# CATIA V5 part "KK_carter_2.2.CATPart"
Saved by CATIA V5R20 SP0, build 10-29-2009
Part number: carter_2.2
Bounding box of the stored display mesh (mm): x -14.5 to 19.5, y 75 to 250, z -25 to 50
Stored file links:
  G:\Khaled_CFAO_2011\ST2M\ST2M_GR2\aandujar\Khaled\CAD_thinkMOTION\KK_carter_2.2.CATPart
  G:\Khaled_CFAO_2011\ST2M\ST2M_GR2\aandujar\Khaled\CAD_thinkMOTION\KK_Aandujar.CATProduct
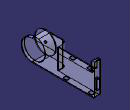
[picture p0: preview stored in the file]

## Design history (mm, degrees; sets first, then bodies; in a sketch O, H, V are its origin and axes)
WSupportSet1: ActiveGrid {3dwsupport RefPoint {point stored without definition}, 3DWOS ({wsupport Support xy-plane, RefPoint {3dwsupport}, GridIn {cartgrid Value 100, Stepbid1 0, Value 100, Stepbid2 0, Direction (1, 0, 0)}, GeometricData ({line type PtDir, Direction (1, 0, 0), Support xy-plane}; {line type PtDir, Direction (0, 1, 0), Support yz-plane})}; {wsupport Support yz-plane, RefPoint {3dwsupport}, GridIn {cartgrid Value 100, Stepbid1 0, Value 100, Stepbid2 0, Direction (0, 1, 0)}, GeometricData ({line type PtDir, Direction (0, 1, 0), Support yz-plane}; {line type PtDir, Direction (0, 0, 1), Support zx-plane})}; {wsupport Support zx-plane, RefPoint {3dwsupport}, GridIn {cartgrid Value 100, Stepbid1 0, Value 100, Stepbid2 0, Direction (0, 0, 1)}, GeometricData ({line type PtDir, Direction (0, 0, 1), Support zx-plane}; {line type PtDir, Direction (1, 0, 0), Support xy-plane})}), GeometricData ({line type PtDir, RefPoint {point stored without definition}, Direction (1, 0, 0), Support xy-plane}; {line type PtDir, RefPoint {point stored without definition}, Direction (0, 1, 0), Support yz-plane}; {line type PtDir, RefPoint {point stored without definition}, Direction (0, 0, 1), Support zx-plane})}
Set1
  Sketch1 on Plane1, origin (12.5, 0, 0), H (0, 1, 0), V (0, 0, 1)
    line L1 (100, -25) -> (250, -25)
    line L2 (250, -25) -> (250, 50)
    line L3 (250, 50) -> (242, 50)
    line L4 (242, 50) -> (242, 25)
    line L5 (242, 25) -> (100, 25)
    arc A1 centre (100, 0) radius 25 from (100, 25) to (100, -25) ccw
    point P7 (100, 0)
    reference projected point E1 (100, 0) from Point1
    reference projected point E2 (335, 0) from Point3
    radius A1 = 25
    distance L2 E2 = 85
    length L3 = 8
    length L4 = 25
    horizontal: L1 H, L3 H, L5 H
    vertical: L2 V, L4 V
    tangency: A1 L1, A1 L5
    coincidence: P7 E1
Set2
  Plane1 "Plan.Ref5": linked copy from another document
  Point1 to Point7: linked copy from another document
Body1 (main body)
  Pad1: profile Sketch1, direction (1, 0, 0), length 7
  Shell1: IntOffset 1, Face start face of Pad1, ExtOffset 0
  Sketch2 on Plane1, origin (12.5, 0, 0), H (0, 1, 0), V (0, 0, 1)
    line L1 (250, -25) -> (250, 50)
    line L2 (250, 50) -> (242, 50)
    line L3 (242, 50) -> (242, 25)
    line L4 (242, 25) -> (100, 25)
    arc A1 centre (100, 0) radius 25 from (100, -25) to (100, 25) ccw
    point P6 (100, 0)
    line L5 (250, -25) -> (100, -25)
    reference projected point E1 (100, 0) from Point1
    reference projected line E2 (250, 50) -> (242, 50) from edge [start face of Pad1 | face of Pad1 from Sketch1.L3]
    reference projected line E3 (250, -25) -> (250, 50) from edge [start face of Pad1 | face of Pad1 from Sketch1.L2]
    reference projected line E4 (242, 50) -> (242, 25) from edge [start face of Pad1 | face of Pad1 from Sketch1.L4]
    radius A1 = 25
    vertical: L1 V, L3 V
    horizontal: L2 H, L4 H
    tangency: A1 L4, L5 A1
    parallelism: L5 L4
    coincidence: E1 P6, L2 E2, L1 E3, L3 E4
  Pad2: profile Sketch2, direction (-1, 0, 0), length 7
  Sketch3 on end face of Pad2, origin (5.5, 0, 0), H (0, -1, 0), V (0, 0, 1)
    arc A1 centre (-100, 0) radius 25 from (-100, 25) to (-100, -25) ccw
    point P1 (-100, 0)
    reference projected point E1 (-100, 0) from Point1
    line L1 (-100, -25) -> (-150, -25)
    line L2 (-150, -25) -> (-150, 25)
    line L3 (-150, 25) -> (-100, 25)
    radius A1 = 25
    coincidence: P1 E1
    tangency: L1 A1, L3 A1
    vertical: L2 V
  Pad3: profile Sketch3, direction (-1, 0, 0), length 20
  Fillet1: radius 10, on edge [face of Pad3 from Sketch3.L2 | end face of Pad3]
  Sketch4 on face of Pad2, origin (0, 250, 0), H (-1, 0, 0), V (0, 0, 1)
    line L1 (-13.5, 10) -> (-8.5, 10)
    line L2 (-8.5, 10) -> (-8.5, -12)
    line L3 (-8.5, -12) -> (-13.5, -12)
    line L4 (-13.5, -12) -> (-13.5, 10)
    reference intersected line E1 through (-12.5, 0) direction (0, -1) from Plane1
    distance L1 L3 = 22
    distance E1 L4 = 1
    distance L4 L2 = 5
    horizontal: L1 H, L3 H
    vertical: L2 V, L4 V
  Pocket1: profile Sketch4, direction (0, -1, 0), length 5
  Fillet2: radius 5, on edge [face of Pad3 | face of Pad2]
  Fillet3: radius 2.5, on edge [face of Pad2 | face of Pad2]
  Fillet4: radius 1, on edge [face of Pad2 | face of Pad2]
  Fillet5: radius 3, on edge [face of Pad2 | face of Pad3]
  Sketch5 on face of Pad3, origin (0, 0, 25), H (1, 0, 0), V (0, 1, 0)
    line L1 (7.5, 237) -> (7.5, 227)
    reference projected point E1 (12.5, 232) from Point4
    line L2 (7.5, 237) -> (15.5, 237)
    line L3 (15.5, 237) -> (15.5, 227)
    line L4 (15.5, 227) -> (7.5, 227)
    reference projected point E2 (12.5, 232) from Point4
    reference projected point E3 (12.5, 232) from Point4
    reference projected point E4 (12.5, 232) from Point4
    distance L1 E1 = 5
    distance L3 E2 = 3
    distance L4 E3 = 5
    distance L2 E4 = 5
    vertical: L1 V, L3 V
    horizontal: L2 H
    parallelism: L4 L2
  Pocket2: profile Sketch5, direction (0, 0, -1), length 5
  Sketch6 on face of Pad3, origin (0, 0, 25), H (1, 0, 0), V (0, 1, 0)
    line L1 (7.5, 195) -> (15.5, 195)
    line L2 (15.5, 195) -> (15.5, 185)
    line L3 (15.5, 185) -> (7.5, 185)
    line L4 (7.5, 185) -> (7.5, 195)
    reference projected point E1 (12.5, 190) from Point5
    reference projected point E2 (12.5, 190) from Point5
    reference projected point E3 (12.5, 190) from Point5
    reference projected point E4 (12.5, 190) from Point5
    distance L4 E1 = 5
    distance L2 E2 = 3
    distance L1 E3 = 5
    distance L3 E4 = 5
    horizontal: L1 H, L3 H
    vertical: L2 V, L4 V
  Pocket3: profile Sketch6, direction (0, 0, -1), length 5
  Sketch7 on face of Pad3, origin (0, 0, -25), H (1, 0, 0), V (0, -1, 0)
    line L1 (7.5, -170) -> (15.5, -170)
    line L2 (15.5, -170) -> (15.5, -180)
    line L3 (15.5, -180) -> (7.5, -180)
    line L4 (7.5, -180) -> (7.5, -170)
    reference projected point E1 (12.5, -175) from Point6
    reference projected point E2 (12.5, -175) from Point6
    reference projected point E3 (12.5, -175) from Point6
    reference projected point E4 (12.5, -175) from Point6
    distance L2 E1 = 3
    distance L4 E2 = 5
    distance L1 E3 = 5
    distance L3 E4 = 5
    horizontal: L1 H, L3 H
    vertical: L2 V, L4 V
  Pocket4: profile Sketch7, direction (0, 0, 1), length 5
  Sketch8 on face of Pad3, origin (0, 0, -25), H (1, 0, 0), V (0, -1, 0)
    line L1 (7.5, -230) -> (15.5, -230)
    line L2 (15.5, -230) -> (15.5, -240)
    line L3 (15.5, -240) -> (7.5, -240)
    line L4 (7.5, -240) -> (7.5, -230)
    reference projected point E1 (12.5, -235) from Point7
    reference projected point E2 (12.5, -235) from Point7
    reference projected point E3 (12.5, -235) from Point7
    reference projected point E4 (12.5, -235) from Point7
    distance L2 E1 = 3
    distance L4 E2 = 5
    distance L1 E3 = 5
    distance L3 E4 = 5
    horizontal: L1 H, L3 H
    vertical: L2 V, L4 V
  Pocket5: profile Sketch8, direction (0, 0, 1), length 5
  Shell2: IntOffset 1, Face (start face of Pad2; face of Pocket5 from Sketch8.L4; face of Pocket5 from Sketch8.L1; face of Pocket5 from Sketch8.L3; end face of Pocket5; face of Pocket2 from Sketch5.L1; face of Pocket2 from Sketch5.L2; face of Pocket2 from Sketch5.L4; end face of Pocket2; end face of Pocket3; face of Pocket3 from Sketch6.L3; face of Pocket3 from Sketch6.L4; face of Pocket3 from Sketch6.L1; end face of Pocket4; face of Pocket4 from Sketch7.L1; face of Pocket4 from Sketch7.L4; face of Pocket4 from Sketch7.L3), ExtOffset 0
  Sketch9 on end face of Pad3, origin (-14.5, 0, 0), H (0, -1, 0), V (0, 0, 1)
    circle A1 centre (-100, 0) radius 25
    point P1 (-100, 0)
    reference projected point E1 (-100, 0) from Point1
    radius A1 = 25
    coincidence: P1 E1
  Pad4: profile Sketch9, direction (1, 0, 0), length 2
  Sketch10 on face of Pad4, origin (-14.5, 0, 0), H (0, -1, 0), V (0, 0, 1)
    circle A1 centre (-100, 0) radius 2.5
    point P1 (-100, 0)
    reference projected point E1 (-100, 0) from Point1
    radius A1 = 2.5
    coincidence: P1 E1
  Pocket6: profile Sketch10, direction (1, 0, 0), through (limit type 6)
